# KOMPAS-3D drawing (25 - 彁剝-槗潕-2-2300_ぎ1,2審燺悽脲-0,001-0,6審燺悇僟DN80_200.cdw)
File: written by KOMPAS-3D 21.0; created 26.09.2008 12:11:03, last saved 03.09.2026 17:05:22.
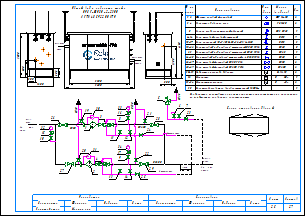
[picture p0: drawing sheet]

Sheets 1-2: A3, landscape

Document properties: Наименование: Макро:21; Автор: RaskoAdmin; Форматы листов документа: 2xA3; Полное имя файла: \\UR38nt01\Departments\КТО\КБ ПУРДГ\Заявки\Прайс-лист на типовые шкафы ГРПШ\ПРДГ_стандарт_20_03_2026\ПРДГ с РДГ(Н, В)\ПРДГ-ШУЭО-2-2300_до1,2МПа_Рвых-0,001-0,6МПа_РДГ_DN80_200.cdw

Title block, sheet 1: Наименование: Пункт учета газа / ПУГ-Ш-400-Р / ЛГТИ.485922.001ТУ; designation: ЛГТИ.03.4411141; sheet number: 1; Количество листов документа: 2; organisation: ООО "ЭЛЬСТЕР Газэлектроника"; Форматы листов документа: A3; stored path: C:\Рабочие документы\Компас\ПУГ\Схема.cdw; Разработал: Устинов; Проверил: Кошкин; Утвердил: Кошкин
Title block, sheet 2: sheet number: 2; stored path: D:\Рабочие документы\Заявки\ПУРДГ\ПУРДГ-ШУЭО-2-100-Р 4411220.cdw; designation, second copy: ЛГТИ.03.4411141-

Views: Вид 1, Вид 2
Referenced files: wcvoit.frw
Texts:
  Normal
  № на
  схеме
  Усл.
  обозн.
  Марка
  (модель)
  Кол.
  Фильтр газовый фланцевый
  ФГ 16-80
  Регулятор давления газа
  РДГ-50
  Клапан предохранительный сбросной
  ПСК DN25
  Кран шаровой газовый латунный
  DN15
  Кран кнопочный VE-РАСКО-НЗ-1,6-G1/2-М20
  Кран шаровой "под приварку" штуцерный DN20 PN16
  Кран шаровой "под приварку" штуцерный DN25 PN16
  Кран шаровой "под приварку" штуцерный п/п DN20 PN16
  DN20
  DN25
  Кран шаровой фланцевый DN80 PN16
  Кран шаровой фланцевый DN200 PN16
  DN80
  DN200
  Индикатор перепада давления
  Delta 15
  Манометр
  Манометр-напоромер
  Электрообогреватель взрывозащищенный 1200Вт
  0...     МПа
  0...     кПа
  Общий вид и габариты шкафа
  ПРДГ-ШУЭО-2-2300
  Выход газа
  Вход газа
  logo-rasko-ge.png
  Вход
  газа
  PDI
  Выход
  Р=     кПа
  DN50
  Импульс DN20
  ≥5DN
  HYSWLongFangSong
  Р=       МПа
  Схема открывания дверей
  Предприятие изготовитель может заменять комплектующие на аналогичные,
  не ухудшающие заявленных характеристик.
  Должность
  Конструктор
  Фамилия
  Подпись
  Дата
  Согласовано
  Максимкин
  Лист
  Листов
  POLYLINE_STYLE_0.18_RGB_0_0_0
  POLYLINE_STYLE_0.50_RGB_0_0_0
  POLYLINE_STYLE_0.34_RGB_0_0_0
  PHANTOM_RGB_0_0_0_SC_1_THICK_0.18
  K5LT_THIN_RGB_0_0_0_THICK_0.18
  K5LT32769_RGB_0_0_0_THICK_0.18
  K5LT12_RGB_0_0_0_SC_1_THICK_0.18
  K5LT_DASHED_RGB_0_0_0_SC_1_THICK_0.18
  ACISOTGL_RGB_0_0_0_SC_0.8_THICK_0.25
  CONTINUOUS_RGB_0_127_31_THICK_0.3
  CONTINUOUS_RGB_0_0_255_THICK_0.35
  CONTINUOUS_RGB_255_0_0_THICK_0.35
  POLYLINE_STYLE_0.25_RGB_0_0_0
  CONTINUOUS_RGB_0_0_0_THICK_0.5
  POLYLINE_STYLE_0.35_RGB_0_0_255
  CONTINUOUS_RGB_0_0_0_THICK_0.4
  CONTINUOUS_RGB_0_0_0_THICK_0.35
  Без оформления
Dimensions and other numbers on the sheet: 1; 1, 2; 2; 3, 4; 5; 6-14; 9; 15-17; 3; 18-22; 23; 24-25; 26-27; 28-29; 30-31; 32; 33-34; 35; 500; 1200; 305; 2000; 3600; 4130; 3300; 4; 10; 27; 28; 29; 8; 12; 19; 20; 21; 22; 25; 24; 30; 31; 15; 16; 26; 6; 7; 11; 14; 13; 33; 17; 34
